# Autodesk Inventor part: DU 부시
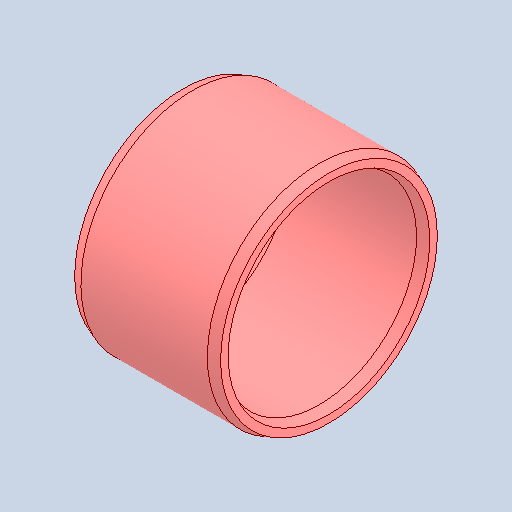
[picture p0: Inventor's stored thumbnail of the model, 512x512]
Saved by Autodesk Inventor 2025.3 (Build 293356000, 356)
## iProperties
Created: 2025-10
Part Number: DU 부시
Material: 스테인리스스틸
Document SubType Name: Modeling
Designer: PC-13
Density: 8 g/cm^3
Appearance: 기본값
Author: jhkim
Sending System: Autodesk Inventor 2026
Preprocessor: ST-DEVELOPER v20.1
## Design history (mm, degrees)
feature "솔리드1"
node "솔리드2"
